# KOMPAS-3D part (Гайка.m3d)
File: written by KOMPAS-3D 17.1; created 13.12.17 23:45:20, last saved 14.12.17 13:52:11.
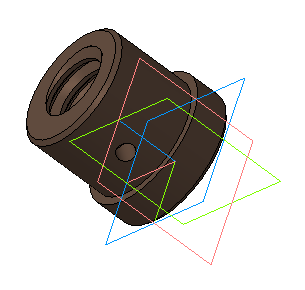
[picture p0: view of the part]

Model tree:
1. Операция без истории:1
2. Фаска:1
     Угол = 45; Длина 1 = 1.5; Длина 2 = 1.5
3. Фаска:2
     Угол = 45; Длина 1 = 1.5; Длина 2 = 1.5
